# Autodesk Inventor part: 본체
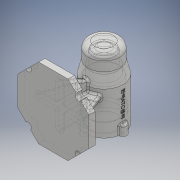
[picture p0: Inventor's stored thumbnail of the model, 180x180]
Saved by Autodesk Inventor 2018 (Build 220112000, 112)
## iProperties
Created: 2019-12
Part Number: 본체
Material: Generic
Document SubType Name: Modeling
Designer: Administrator
Density: 1 g/cm^3
Appearance: Default
Author: Administrator
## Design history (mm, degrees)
sketch "스케치1"
  geometry: L1 (56.037, -23.106)-(23.286, -55.963); L2 (23.286, -55.963)-(-23.106, -56.037); L3 (-23.106, -56.037)-(-55.963, -23.286); L4 (-55.963, -23.286)-(-56.037, 23.106); L5 (-56.037, 23.106)-(-23.286, 55.963); L6 (-23.286, 55.963)-(23.106, 56.037); L7 (23.106, 56.037)-(55.963, 23.286); L8 (55.963, 23.286)-(56.037, -23.106); 1 further point
  constraints: 16 end point
  dimensions: "d0" = 112 distance between parallel lines of L6 L2
extrude "돌출1" new body sketch "스케치1" distance "d1" = 10; taper "d2" = 0 deg
sketch "스케치2"
  geometry: L1 (0, -23.286)-(0, 23.106) reference; L2 (80, -55.359)-(110, -55.359); L3 (110, -55.359)-(110, 11.641); L4 (105, 31.641)-(105, 56.641); L5 (105, 56.641)-(80, 56.641); L6 (80, -55.359)-(80, 56.641); L7 (110, 11.641)-(105, 31.641); 1 further point
  constraints: 12 end point, 1 horizontal, 1 perpendicular, 1 vertical
  dimensions: "d4" = 112 distance between parallel lines of L5 L2; "d6" = 80 distance between parallel lines of L1 L6; "d7" = 50 diameter of L4 L6; "d9" = 60 diameter of L3 L6; "d10" = 67 distance of L2.end L3.end; "d11" = 25 distance of L4.start L4.end
revolve "회전1" sketch "스케치2" stored, may be unused: angle "d12" = 90 deg
fillet "모깎기1" dims "d13" = 10
sketch "스케치4"
  geometry: L1 (53.214, -30.963)-(53.214, 17.886); L2 (53.214, 17.886)-(10, 38.037); L3 (10, -30.963)-(53.214, -30.963); L4 (0, -55.963)-(10, -55.963) reference; L5 (0, 56.037)-(10, 56.037) reference; L6 (10, 38.037)-(10, -30.963); L7 (10, 23.286)-(10, 56.037) reference
  constraints: 8 end point, 1 collinear
  dimensions: "d32" = 25 distance between parallel lines of L3 L4; "d33" = 18 distance from line of L5 L2.end; "d92" = 115 deg angle of L7 L2
extrude "돌출2" join sketch "스케치4" stored distance "d34" = 8; taper "d35" = 0 deg
sketch "스케치5"
  geometry: L1 (18.528, 58.105)-(-18.454, 58.105); L2 (-18.454, 58.105)-(-35.963, 10); L3 (36.037, 10)-(18.528, 58.105); L4 (-55.963, 0)-(-55.963, 10) reference; L5 (56.037, 0)-(56.037, 10) reference; L6 (36.037, 10)-(-35.963, 10); 1 further point
  constraints: 8 end point, 2 horizontal
  dimensions: "d38" = 20 distance from line of L2.end L4; "d39" = 20 distance from line of L5 L3.start
extrude "돌출3" join sketch "스케치5" stored distance "d40" = 8; taper "d41" = 0 deg
sketch "스케치6"
  geometry: L1 (-23.106, -56.037)-(-55.963, -23.286) reference; L2 (56.037, -23.106)-(23.286, -55.963) reference; L3 (23.106, 56.037)-(55.963, 23.286) reference; L4 (-56.037, 23.106)-(-23.286, 55.963) reference; C1 r 5 at (-39.534, -39.662); C2 r 5 at (39.662, -39.534); C3 r 5 at (39.534, 39.662); C4 r 5 at (-39.662, 39.534); 1 further point
  constraints: 4 centre point, 4 midpoint
  dimensions: "d43" = 10 diameter of C1; "d44" = 10 diameter of C2; "d45" = 10 diameter of C3; "d46" = 10 diameter of C4
extrude "돌출4" cut sketch "스케치6" extent not by distance; stored distance "d51" = 8; taper "d52" = 0 deg
sketch "스케치7"
  geometry: L1 (50, -55.359)-(110, -55.359) reference; L2 (80, -55.359)-(101, -55.359); L3 (101, -55.359)-(101, -40.359); L4 (101, -40.359)-(80, -40.359); L5 (80, -40.359)-(80, -55.359); L6 (80, -40.359)-(104, -40.359); L7 (104, -40.359)-(104, 13.641); L8 (104, 13.641)-(80, 13.641); L9 (80, 13.641)-(80, -40.359); L10 (80, 13.641)-(101, 13.641); L11 (101, 13.641)-(101, 25.641); L12 (101, 25.641)-(80, 25.641); L13 (80, 25.641)-(80, 13.641); L14 (80, 25.641)-(97.5, 25.641); L15 (97.5, 25.641)-(97.5, 43.641); L16 (97.5, 43.641)-(80, 43.641); L17 (80, 43.641)-(80, 25.641); L18 (80, 43.641)-(96, 43.641); L19 (96, 43.641)-(96, 47.641); L20 (96, 47.641)-(80, 47.641); L21 (80, 47.641)-(80, 43.641); L22 (80, 47.641)-(90.5, 47.641); L23 (90.5, 47.641)-(90.5, 50.641); L24 (90.5, 50.641)-(80, 50.641); L25 (80, 50.641)-(80, 47.641); 1 further point
  constraints: 48 end point, 12 parallel, 6 horizontal, 6 perpendicular, 1 midpoint
  dimensions: "d53" = 15 distance between parallel lines of L4 L2; "d54" = 42 diameter of L3 L5; "d55" = 48 diameter of L7 L9; "d56" = 42 diameter of L11 L13; "d57" = 54 distance of L6.end L7.end; "d58" = 12 distance of L10.end L11.end; "d59" = 18 distance of L14.end L15.end; "d60" = 35 diameter of L15 L17; "d61" = 4 distance of L18.end L19.end; "d62" = 32 diameter of L19 L21; "d63" = 21 diameter of L23 L25; "d64" = 3 distance of L22.end L23.end
revolve "회전2" sketch "스케치7" stored, may be unused: angle "d65" = 90 deg
fillet "모깎기2" dims "d66" = 3
chamfer "모따기1" distance "d67" = 1; stored, may be unused: second distance "d68" = 2, angle "d69" = 45 deg
sketch "스케치8"
  geometry: C1 r 6 at (0, 30); C2 r 6 at (30, 0); C3 r 6 at (-30, 0); C4 r 6 at (0, -30); A1 r 30 centre (0, 0) between (0, 30) and (30, 0) reference; 1 further point
  constraints: 4 centre point, 2 point on circle
  dimensions: "d70" = 12 diameter of C1; "d71" = 12 diameter of C2
extrude "돌출5" join sketch "스케치8" distance "d72" = 16; taper "d73" = 0 deg
sketch "스케치9"
  geometry: A1 r 6 centre (-30, -30) between (-29.4, -24.03) and (-29.4, -35.97) reference; A2 r 6 centre (0, 0) between (5.97, -0.6) and (-5.97, -0.6) reference; A3 r 6 centre (30, -30) between (29.4, -35.97) and (29.4, -24.03) reference; A4 r 6 centre (0, -60) between (-5.97, -59.4) and (5.97, -59.4) reference; 5 further points
  constraints: 4 coincident
hole "구멍1" sketch "스케치9" at (-30, -30), (0, 0), (30, -30), (0, -60) diameter "d74" = 3.242; stored, may be unused: countersink angle "d78" = 90 deg, drill point angle "d80" = 118 deg; dims "d75" = 8, "d76" = 4, "d77" = 2, "d79" = 11
fillet "모깎기3" dims "d81" = 3
fillet "모깎기4" dims "d82" = 3
fillet "모깎기5" dims "d83" = 3
fillet "모깎기6" dims "d84" = 3
fillet "모깎기7" dims "d85" = 3
fillet "모깎기8" dims "d86" = 0.3
node "작업 평면1"
sketch "스케치10"
  geometry: L1 (8.017, -33.5)-(28.909, -33.5) reference; L2 (-15, 78.5)-(15, 78.5) reference; 2 further points
  constraints: 1 other
  dimensions: "d87" = 41 distance from line of L1 point (0, 7.5)
feature "엠보싱1" sketch "스케치10" dims "d0" = 112, "d13" = 10, "d88" = 0.5, "d89" = 0
fillet "모깎기9" dims "d90" = 1
fillet "모깎기10" dims "d91" = 3
node "솔리드1"
other parameters: "d22" = 4, "d23" = 4
